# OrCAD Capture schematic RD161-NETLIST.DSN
size A3
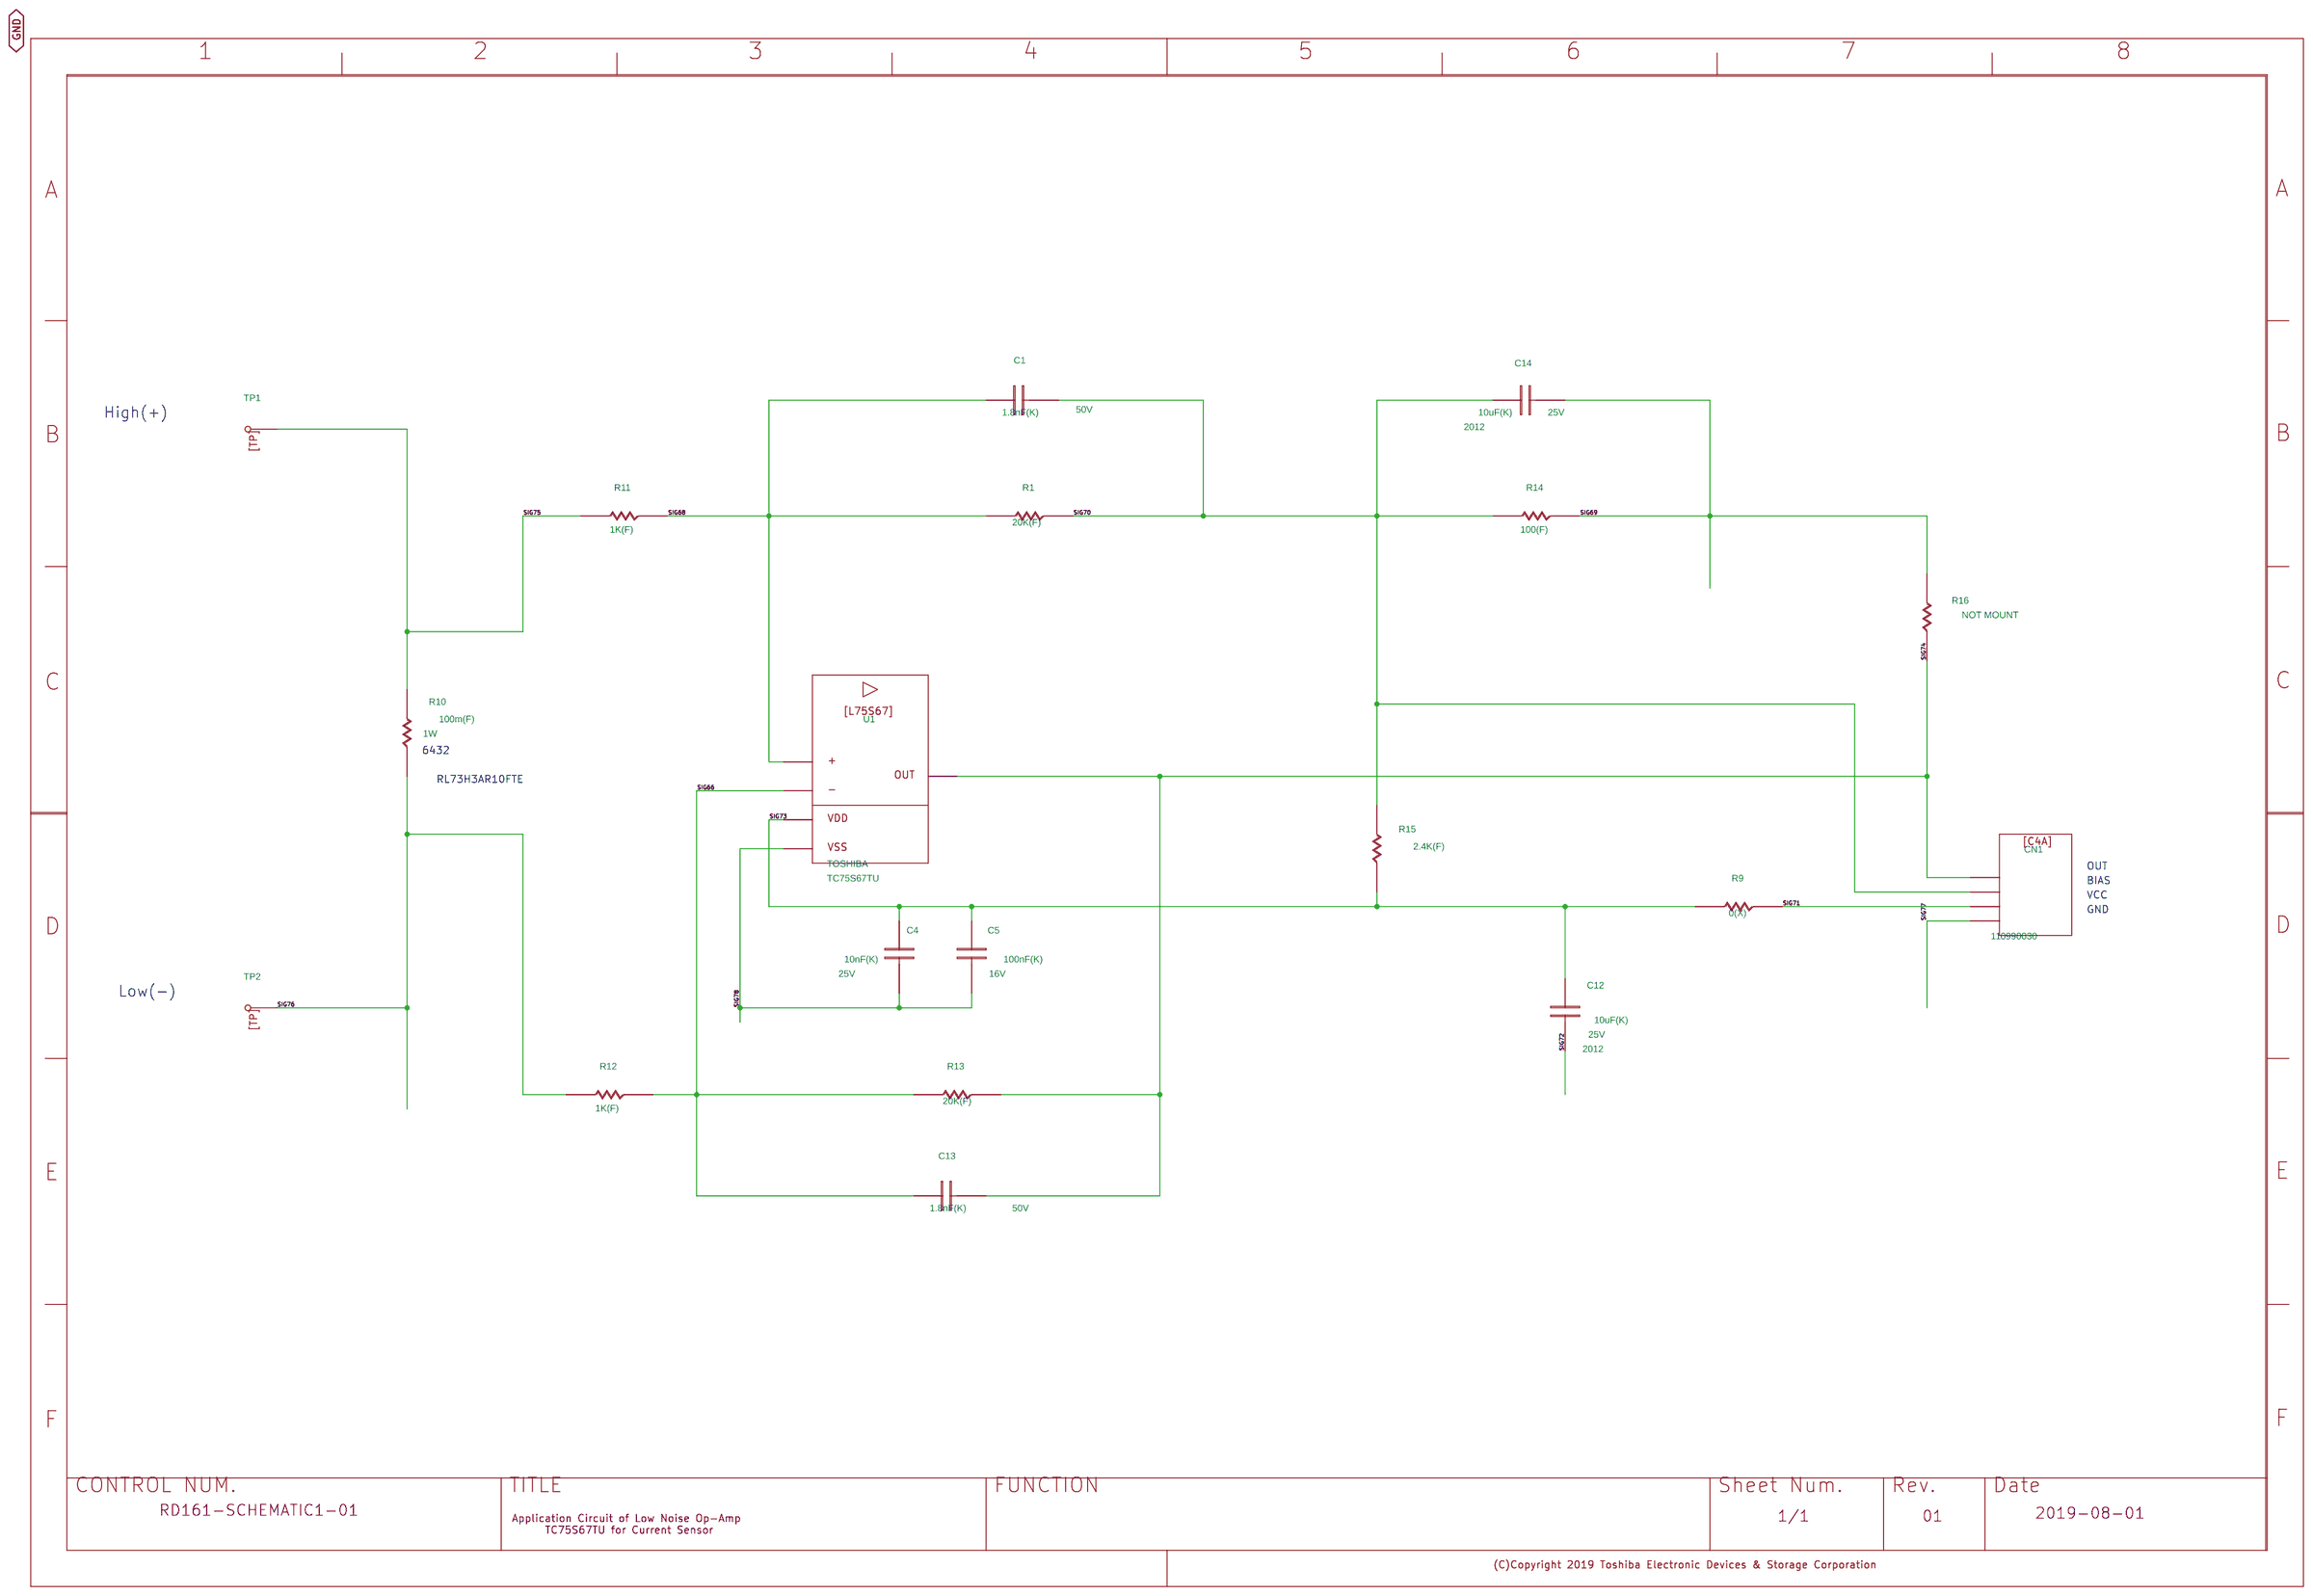
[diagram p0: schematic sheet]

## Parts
C1  C
C4  C
C5  C
C12  C
C13  C
C14  C
CN1  C4A
R1  R
R9  R
R10  R
R11  R
R12  R
R13  R
R14  R
R15  R
R16  R
TP1  TP
TP2  TP
U1  L75S67
U?#1  WAKU_DEF100

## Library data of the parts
C1 C13 = C: CDBNAME: GDM030000385; COMPONENTNAME: GDM030000385_package; COMPONENTTYPE: 4; FUNCTION: GDM030000385; GCOUNT: 1; MAXGCOUNT: 1; PARTNAME: GDM030000385; SIZECODESMD: 1005; VAL1: 1.8nF(K); VAL2: 50V
C4 = C: CDBNAME: GAS030000012; COMPONENTNAME: GAS030000012_package; COMPONENTTYPE: 4; FUNCTION: GAS030000012; GCOUNT: 1; MAXGCOUNT: 1; PARTNAME: GAS030000012; SIZECODESMD: 1005; VAL1: 10nF(K); VAL2: 25V
C5 = C: CDBNAME: GDM030002515; COMPONENTNAME: GDM030002515_package; COMPONENTTYPE: 4; FUNCTION: GDM030002515; GCOUNT: 1; MAXGCOUNT: 1; PARTNAME: GDM030002515; SIZECODESMD: 1005; VAL1: 100nF(K); VAL2: 16V
C12 C14 = C: CDBNAME: GDM030002136; COMPONENTNAME: GDM030002136_package; COMPONENTTYPE: 4; FUNCTION: GDM030002136; GCOUNT: 1; MAXGCOUNT: 1; PARTNAME: GDM030002136; SIZECODESMD: 2012; VAL1: 10uF(K); VAL2: 25V
CN1 = C4A: CDBNAME: K22S001P; COMPONENTNAME: K22S001P_package; COMPONENTTYPE: 4; FUNCTION: K22S001P; GCOUNT: 1; MAXGCOUNT: 1; OUMEPARTTYPE: CN; PARTNAME: K22S001P; VAL3: 110990030
R1 R13 = R: CDBNAME: G36010118152; COMPONENTNAME: G36010118152_package; COMPONENTTYPE: 4; FUNCTION: G36010118152; GCOUNT: 1; MAXGCOUNT: 1; PARTNAME: G36010118152; SIZECODESMD: 1005; VAL1: 20K(F); VAL2: 100mW
R9 = R: CDBNAME: GDM010000374; COMPONENTNAME: GDM010000374_package; COMPONENTTYPE: 4; FUNCTION: GDM010000374; GCOUNT: 1; MAXGCOUNT: 1; PARTNAME: GDM010000374; SIZECODESMD: 1005; VAL1: 0(X); VAL2: 1A
R10 = R: CDBNAME: K0100130; COMPONENTNAME: K0100130_package; COMPONENTTYPE: 4; FUNCTION: K0100130; GCOUNT: 1; MAXGCOUNT: 1; PARTNAME: K0100130; SIZECODESMD: 6332; VAL1: 100m(F); VAL2: 1W; VAL3: RL73H3AR10FTE
R11 R12 = R: CDBNAME: GDM010000088; COMPONENTNAME: GDM010000088_package; COMPONENTTYPE: 4; FUNCTION: GDM010000088; GCOUNT: 1; MAXGCOUNT: 1; PARTNAME: GDM010000088; SIZECODESMD: 1005; VAL1: 1K(F); VAL2: 100mW
R14 = R: CDBNAME: G36010118534; COMPONENTNAME: G36010118534_package; COMPONENTTYPE: 4; FUNCTION: G36010118534; GCOUNT: 1; MAXGCOUNT: 1; PARTNAME: G36010118534; SIZECODESMD: 1005; VAL1: 100(F); VAL2: 100mW
R15 = R: CDBNAME: G36010118602; COMPONENTNAME: G36010118602_package; COMPONENTTYPE: 4; FUNCTION: G36010118602; GCOUNT: 1; MAXGCOUNT: 1; PARTNAME: G36010118602; SIZECODESMD: 1005; VAL1: 2.4K(F); VAL2: 100mW
R16 = R: CDBNAME: GDM010000374; COMPONENTNAME: GDM010000374_package; COMPONENTTYPE: 4; FUNCTION: GDM010000374; GCOUNT: 1; MAXGCOUNT: 1; NOTMOUNT: NOT MOUNT; PARTNAME: GDM010000374; SIZECODESMD: 1005
TP1 TP2 = TP: CDBNAME: ZS_DE051A; COMPONENTNAME: ZS_DE051A_package; COMPONENTTYPE: 4; FUNCTION: ZS_DE051A; GCOUNT: 1; MAXGCOUNT: 1; PARTNAME: ZS_DE051A
U1 = L75S67: CDBNAME: K47S002A; COMPONENTNAME: K47S002A_package; COMPONENTTYPE: 4; FUNCTION: K47S002A; GCOUNT: 1; MAXGCOUNT: 1; OUMEPARTTYPE: IC; PARTNAME: K47S002A; SAVEAREA0: -72307,-25685,103712,61936; UPDATEDATE: 2015/03/06; UPDATETIME: 13:02:06; UPDATEUSER: 19990028; USERCOMPTEXT3: TOSHIBA; VAL1: TC75S67TU; VAL3: TC75S67TU
U?#1 = WAKU_DEF100: COMPONENTTYPE: 2; DATE: 2019-08-01; DRAWINGNUMBER: RD161-SCHEMATIC1-01; FUNCTION: None; REVISION: 01; SHEETNUMBER: 1/1; TITLE: Application Circuit of Low Noise Op-Amp / TC75S67TU for Current Sensor; UPDATEDATE: 2019/08/22; UPDATETIME: 16:55:41; UPDATEUSER: cae

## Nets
GND: C4.2 C5.2 C12.2 C14.2 CN1.4 R10.2 R12.1 R14.2 R16.1 TP2.1 U1.2
SIG66: C13.1 R12.2 R13.1 U1.3
SIG68: C1.1 R1.1 R11.2 U1.1
SIG70: C1.2 C14.1 CN1.2 R1.2 R14.1 R15.1
SIG71: CN1.3 R9.2
SIG73: C4.1 C5.1 C12.1 R9.1 R15.2 U1.5
SIG74: C13.2 CN1.1 R13.2 R16.2 U1.4
SIG75: R10.1 R11.1 TP1.1

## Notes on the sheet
- High(+)
- 6432
- RL73H3AR10FTE
- OUT
- BIAS
- VCC
- GND
- Low(-)
